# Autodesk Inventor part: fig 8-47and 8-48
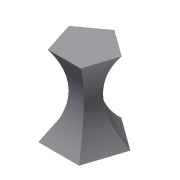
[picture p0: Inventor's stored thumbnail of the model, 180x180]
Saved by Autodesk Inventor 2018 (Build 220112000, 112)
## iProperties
Shininess: 64.0
Length Units: 11269
Angle Units: 11279
Time Units: 11290
Mass Units: 11283
Length Display Precision: 3
Angle Display Precision: 2
Compacted: True
Part Number: fig 8-47and 8-48
Document SubType Name: Modeling
Created: 2002-12
Designer: deepak
Density: 1 g/cm^3
Material: Generic
Appearance: Default
Density: 0.0
Volumn: 0.0
Area: 0.0
PropertySet Name: Model Information
Control State: 0
Master: False
Checked Out: False
Author: deepak
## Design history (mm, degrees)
sketch "Sketch1"
  geometry: L1 (0, 21.819)-(20.751, 6.743); L2 (20.751, 6.743)-(12.825, -17.652); L3 (12.825, -17.652)-(-12.825, -17.652); L4 (-12.825, -17.652)-(-20.751, 6.743); L5 (-20.751, 6.743)-(0, 21.819); 1 further point
  constraints: 10 end point, 9 other
workplane "Work Plane1"
sketch "Sketch2"
  geometry: L1 (0, 8.24)-(7.836, 2.546); L2 (7.836, 2.546)-(4.843, -6.666); L3 (4.843, -6.666)-(-4.843, -6.666); L4 (-4.843, -6.666)-(-7.836, 2.546); L5 (-7.836, 2.546)-(0, 8.24); 1 further point
  constraints: 10 end point, 9 other
workplane "Work Plane2"
sketch "Sketch3"
  geometry: L1 (0, 17.494)-(16.637, 5.406); L2 (16.637, 5.406)-(10.283, -14.153); L3 (10.283, -14.153)-(-10.283, -14.153); L4 (-10.283, -14.153)-(-16.637, 5.406); L5 (-16.637, 5.406)-(0, 17.494); 1 further point
  constraints: 10 end point, 9 other
loft "Loft4" sketch "Sketch3" dims "d20" = 0, "d21" = 90 deg, "d22" = 0, "d23" = 90 deg, "d24" = 0, "d25" = 90 deg
body "Solid1"
other parameters: "d0" = 25, "d1" = 25
